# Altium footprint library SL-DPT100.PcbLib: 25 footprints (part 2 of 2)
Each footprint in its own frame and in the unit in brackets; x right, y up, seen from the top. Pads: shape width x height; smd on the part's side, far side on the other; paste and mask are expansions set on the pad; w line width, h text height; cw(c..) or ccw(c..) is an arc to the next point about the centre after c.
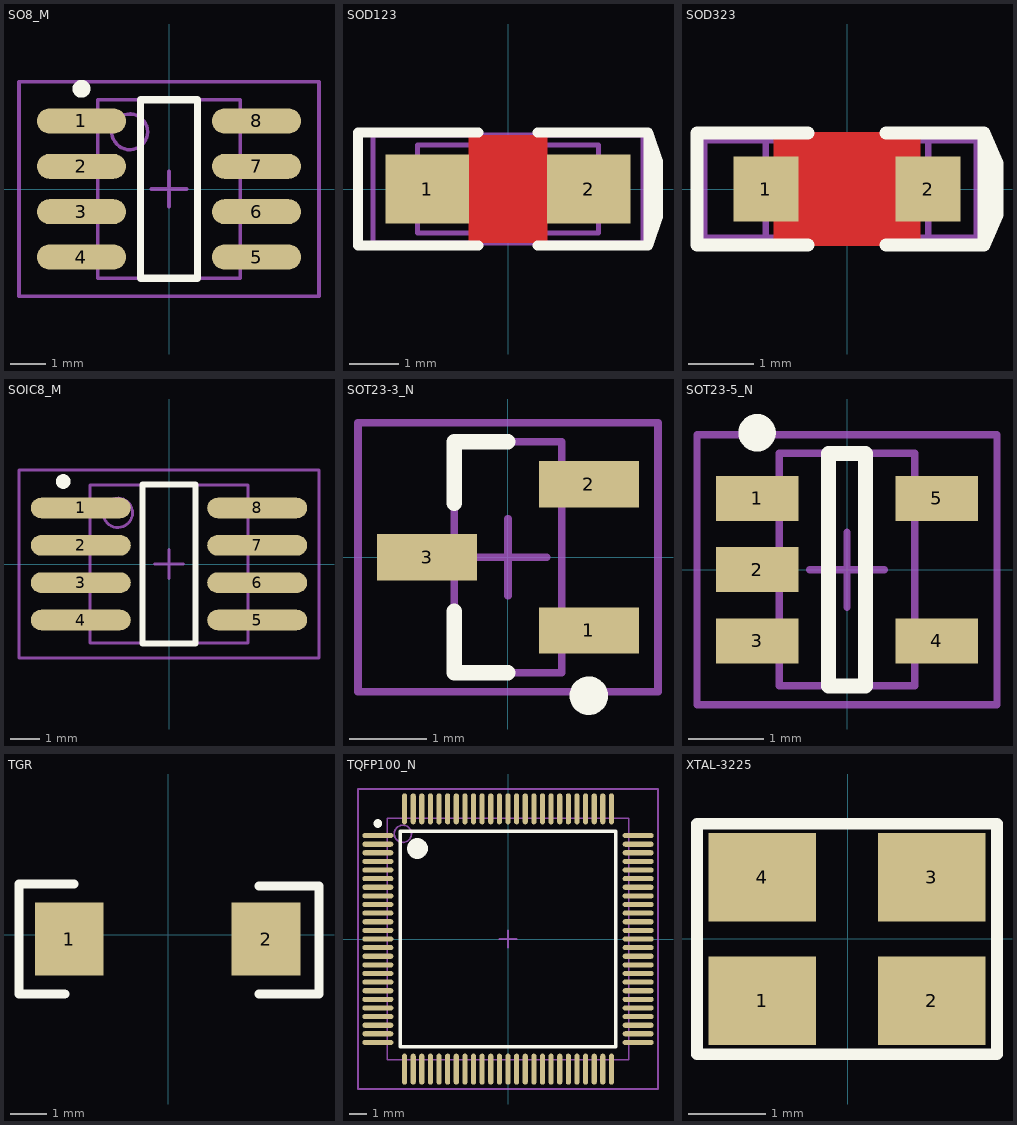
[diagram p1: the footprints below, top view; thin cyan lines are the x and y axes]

## SO8_M [mm] "8-Pin Small Outline Integrated Circuit 1.27 mm Pitch, IPC Low Density"
height 1.75
pads (8):
  oval 2.5x0.7 smd: 1(-2.45,1.905) 2(-2.45,0.635) 3(-2.45,-0.635) 4(-2.45,-1.905) 5(2.45,-1.905) 6(2.45,-0.635) 7(2.45,0.635) 8(2.45,1.905)
Top Overlay:
  circle w0.25: c-2.45,2.805 r0.125
  lines w0.2: -0.8,-2.5 -0.8,2.5 0.8,2.5 0.8,-2.5 -0.8,-2.5
Mechanical 13:
  circle w0.1: c-1.1,1.6 r0.5
  lines w0.1: -2,-2.5 -2,2.5 2,2.5 2,-2.5 -2,-2.5
Mechanical 15:
  lines w0.1: -0.5,0 0.5,0 ; 0,-0.5 0,0.5 ; -4.2,-3 -4.2,3 4.2,3 4.2,-3 -4.2,-3
3D body: height 1.75, standoff 0, extent -2,-2.5 2,2.5

## SOD123 [mm] "SOD-123; 2 Leads; Body 2.7 x 1.6 mm, (LxW)"
height 1.35
pads (2):
  rect 1.7x1.4 smd: 1(-1.65,0) 2(1.65,0)
Top Layer:
  pour cut-out: -0.8,1.1 -0.8,-1.1 0.8,-1.1 0.8,1.1
Top Overlay:
  lines w0.2: -0.6,-1.15 -3.06,-1.15 -3.06,1.15 -0.6,1.15 ; 0.6,-1.15 2.86,-1.15 ; 0.6,1.15 2.86,1.15 ; 2.96,-0.462 2.96,0.485 ; 2.86,-1.15 3.06,-0.575 3.06,0.575 2.86,1.15 ; 2.86,-1.15 2.86,1.15
Mechanical 13:
  lines w0.1: -1.85,-0.9 1.85,-0.9 1.85,0.9 -1.85,0.9 -1.85,-0.9
Mechanical 15:
  lines w0.1: -0.5,0 0.5,0 ; 0,-0.5 0,0.5 ; -2.75,-1.1 2.75,-1.1 2.75,1.1 -2.75,1.1 -2.75,-1.1
3D body: height 1.35, standoff 0, extent -1.85,-0.91 1.85,0.9

## SOD323 [mm] "SOD-323; 2 Leads; Body 2.5 x 1.3 mm, (LxW)"
height 1.35
pads (2):
  rect 1x1 smd: 1(-1.25,0) 2(1.25,0)
Top Layer:
  pour cut-out: -1.125,0.875 -1.125,-0.875 1.125,-0.875 1.125,0.875
Top Overlay:
  lines w0.2: -0.6,-0.86 -2.31,-0.86 -2.31,0.86 -0.6,0.86 ; 0.6,-0.86 2.113,-0.86 ; 0.6,0.86 2.11,0.86 ; 2.21,-0.6 2.21,0.6 ; 2.11,0.86 2.11,-0.86 2.31,-0.4 2.31,0.4 2.11,0.86
Mechanical 13:
  lines w0.1: -1.25,-0.75 -1.25,0.75 1.25,0.75 1.25,-0.75 -1.25,-0.75
Mechanical 15:
  lines w0.1: -0.5,0 0.5,0 ; 0,-0.5 0,0.5 ; -2.2,-0.75 -2.2,0.75 2,0.75 2,-0.75 -2.2,-0.75
3D body: height 1.35, standoff 0, extent -1.25,-0.75 1.25,0.75

## SOIC8_M [mm] "SOIC, 8-Leads, Body 5.4x5.4mm (max), Pitch 1.27mm, IPC Low Density"
height 2.16
pads (8):
  oval 3.4x0.7 smd: 1(-3,1.905) 2(-3,0.635) 3(-3,-0.635) 4(-3,-1.905) 5(3,-1.905) 6(3,-0.635) 7(3,0.635) 8(3,1.905)
Top Overlay:
  circle w0.25: c-3.6,2.805 r0.125
  lines w0.2: -0.9,-2.7 0.9,-2.7 0.9,2.7 -0.9,2.7 -0.9,-2.7
Mechanical 13:
  circle w0.1: c-1.74,1.74 r0.5
  lines w0.1: -2.69,-2.69 2.69,-2.69 2.69,2.69 -2.69,2.69 -2.69,-2.69
Mechanical 15:
  lines w0.1: -0.5,0 0.5,0 ; 0,-0.5 0,0.5 ; -5.1,-3.2 5.1,-3.2 5.1,3.2 -5.1,3.2 -5.1,-3.2
3D body: height 2.16, standoff 0.05, extent -2.69,-2.69 2.69,2.69

## SOT23-3_N [mm] "SOT23, 3-Leads, Body 2.9x1.3mm, Pitch 0.95mm, Lead Span 2.3mm, IPC Medium Density"
height 1.2
pads (3):
  rect 1.3x0.6 smd: 1(1.05,-0.95) 2(1.05,0.95) 3(-1.05,0)
Top Overlay:
  circle w0.25: c1.05,-1.8 r0.125
  lines w0.2: -0.7,-0.7 -0.7,-1.5 0,-1.5 ; -0.7,0.7 -0.7,1.5 0,1.5
Mechanical 13:
  lines w0.1: -0.7,-1.5 0.7,-1.5 0.7,1.5 -0.7,1.5 -0.7,-1.5
Mechanical 15:
  lines w0.1: -0.5,0 0.5,0 ; 0,-0.5 0,0.5 ; -1.95,-1.75 1.95,-1.75 1.95,1.75 -1.95,1.75 -1.95,-1.75
3D body: height 1.2, standoff 0, extent -0.7,-1.5 0.7,1.5

## SOT23-5_N [mm] "SOT23, 5-Leads, Body 2.9x1.6mm, Pitch 0.95mm, Lead Span 2.8mm, IPC Medium Density"
height 1.45
pads (5):
  rect 1.1x0.6 smd: 1(-1.2,0.95) 2(-1.2,0) 3(-1.2,-0.95) 4(1.2,-0.95) 5(1.2,0.95)
Top Overlay:
  circle w0.25: c-1.2,1.825 r0.125
  lines w0.2: -0.25,-1.55 0.25,-1.55 0.25,1.55 -0.25,1.55 -0.25,-1.55
Mechanical 13:
  lines w0.1: -0.9,-1.55 -0.9,1.55 0.9,1.55 0.9,-1.55 -0.9,-1.55
Mechanical 15:
  lines w0.1: -0.5,0 0.5,0 ; 0,-0.5 0,0.5 ; -2,-1.8 -2,1.8 2,1.8 2,-1.8 -2,-1.8
3D body: height 1.45, standoff 0, extent -0.9,-1.55 0.9,1.55

## TGR [mil]
pads (2):
  rect 75x80 smd: 1(-107.94,-4.4) 2(107.07,-4.4)
Top Overlay:
  lines w10: -162.93,-64.4 -112.93,-64.4 ; -162.93,-62.4 -162.93,53.6 ; -162.93,55.6 -102.93,55.6 ; 99.57,-64.4 165,-64.4 165,53.6 99.57,53.6

## TQFP100_N [mm] "100-Pin Thin Quad Flat Pack 0.5 mm Pitch, IPC Medium Density"
height 1.6
pads (100):
  oval 1.8x0.3 smd: 1(-7.55,6) 2(-7.55,5.5) 3(-7.55,5) 4(-7.55,4.5) 5(-7.55,4) 6(-7.55,3.5) 7(-7.55,3) 8(-7.55,2.5) 9(-7.55,2) 10(-7.55,1.5) 11(-7.55,1) 12(-7.55,0.5) 13(-7.55,0) 14(-7.55,-0.5) 15(-7.55,-1) 16(-7.55,-1.5) 17(-7.55,-2) 18(-7.55,-2.5) 19(-7.55,-3) 20(-7.55,-3.5) 21(-7.55,-4) 22(-7.55,-4.5) 23(-7.55,-5) 24(-7.55,-5.5) 25(-7.55,-6) 51(7.55,-6) 52(7.55,-5.5) 53(7.55,-5) 54(7.55,-4.5) 55(7.55,-4) 56(7.55,-3.5) 57(7.55,-3) 58(7.55,-2.5) 59(7.55,-2) 60(7.55,-1.5) 61(7.55,-1) 62(7.55,-0.5) 63(7.55,0) 64(7.55,0.5) 65(7.55,1) 66(7.55,1.5) 67(7.55,2) 68(7.55,2.5) 69(7.55,3) 70(7.55,3.5) 71(7.55,4) 72(7.55,4.5) 73(7.55,5) 74(7.55,5.5) 75(7.55,6)
  oval 0.3x1.8 smd: 26(-6,-7.55) 27(-5.5,-7.55) 28(-5,-7.55) 29(-4.5,-7.55) 30(-4,-7.55) 31(-3.5,-7.55) 32(-3,-7.55) 33(-2.5,-7.55) 34(-2,-7.55) 35(-1.5,-7.55) 36(-1,-7.55) 37(-0.5,-7.55) 38(0,-7.55) 39(0.5,-7.55) 40(1,-7.55) 41(1.5,-7.55) 42(2,-7.55) 43(2.5,-7.55) 44(3,-7.55) 45(3.5,-7.55) 46(4,-7.55) 47(4.5,-7.55) 48(5,-7.55) 49(5.5,-7.55) 50(6,-7.55) 76(6,7.55) 77(5.5,7.55) 78(5,7.55) 79(4.5,7.55) 80(4,7.55) 81(3.5,7.55) 82(3,7.55) 83(2.5,7.55) 84(2,7.55) 85(1.5,7.55) 86(1,7.55) 87(0.5,7.55) 88(0,7.55) 89(-0.5,7.55) 90(-1,7.55) 91(-1.5,7.55) 92(-2,7.55) 93(-2.5,7.55) 94(-3,7.55) 95(-3.5,7.55) 96(-4,7.55) 97(-4.5,7.55) 98(-5,7.55) 99(-5.5,7.55) 100(-6,7.55)
Top Overlay:
  circle w0.6: c-5.25,5.25 r0.3
  circle w0.25: c-7.55,6.7 r0.125
  lines w0.2: -6.25,-6.25 6.25,-6.25 6.25,6.25 -6.25,6.25 -6.25,-6.25
Mechanical 13:
  circle w0.1: c-6.1,6.1 r0.5
  lines w0.1: -7,-7 7,-7 7,7 -7,7 -7,-7
Mechanical 15:
  lines w0.1: -0.5,0 0.5,0 ; 0,-0.5 0,0.5 ; -8.7,-8.7 8.7,-8.7 8.7,8.7 -8.7,8.7 -8.7,-8.7
3D body: height 1.6, standoff 0, extent -7,-7 7,7

## XTAL-3225 [mm]
height 1.6
pads (4):
  rect 1.4x1.15 smd: 1(-1.108,-0.802) 2(1.092,-0.802) 3(1.092,0.798) 4(-1.108,0.798)
Top Overlay:
  lines w0.152: -1.958,-1.502 1.942,-1.502 1.942,1.498 -1.958,1.498 -1.958,-1.502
